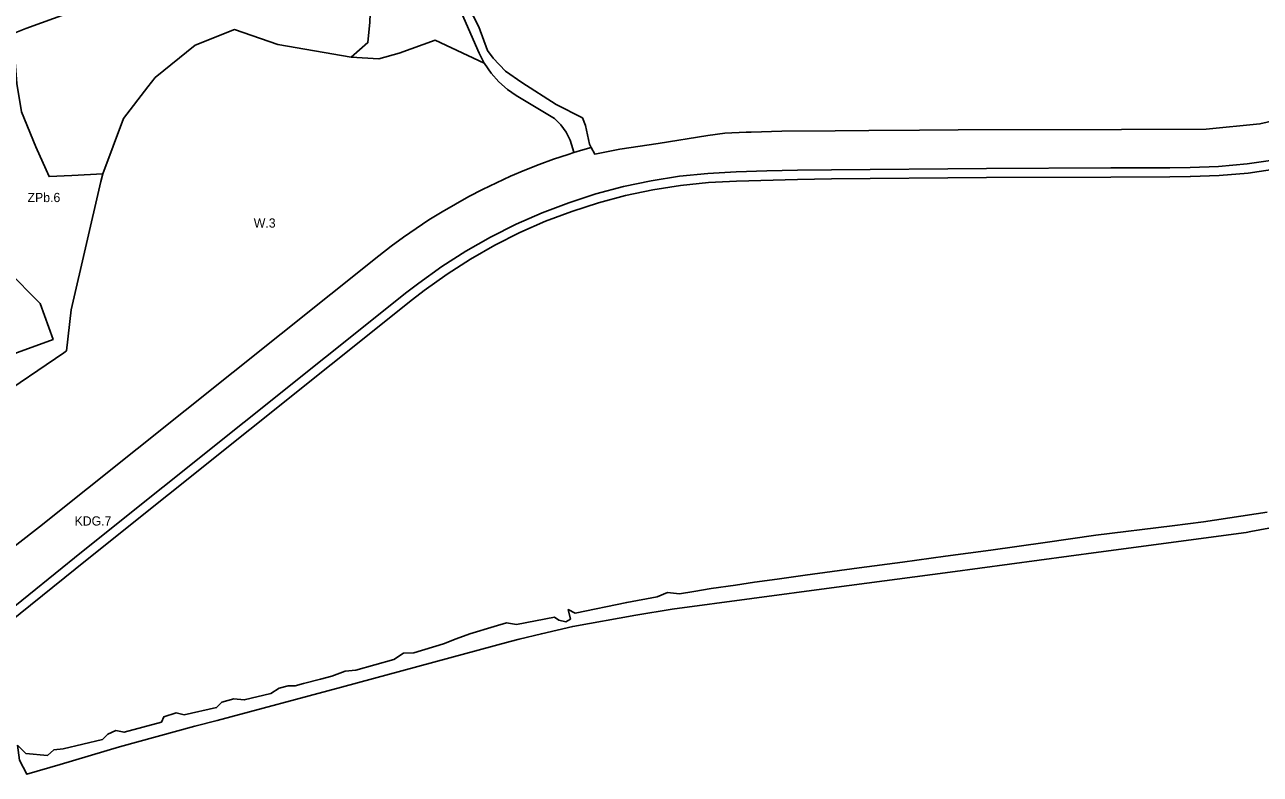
# Model space of a CAD drawing. Extents: x 7414808 to 7417449, y 5544732 to 5546764.
# Drawn here: x 7415896 to 7416568, y 5545062 to 5545469 of the extents above; entities that cross this region are included whole.
import ezdxf

# ---------------------------------------------------------------- set-up
doc = ezdxf.new("R2010")
doc.units = 0
for name, color, linetype in [('LIN_Linie Rozgraniczajace', 7, 'Continuous'), ('LIN_nieprzekraczale linie zabudowy', 7, 'Continuous'), ('TXT_Oznaczenia Przeznaczenia', 7, 'Continuous')]:
    doc.layers.add(name, color=color, linetype=linetype)

msp = doc.modelspace()

# ---------------------------------------------------------------- linework, layer by layer
at = {"layer": 'LIN_Linie Rozgraniczajace'}
for points in [[(7416073.13, 5545451.31), (7416082.32, 5545459.31), (7416083.36, 5545470.35), (7416084.04, 5545488.79), (7416084.22, 5545493.67), (7416088.82, 5545518.65), (7416087.12, 5545521.07), (7416090.29, 5545545.12), (7416089.03, 5545552.44), (7416091.1, 5545559), (7416097.95, 5545570.39), (7416098.86, 5545573.49), (7416101.69, 5545583.08), (7416103.92, 5545582.48), (7416110.68, 5545580.67), (7416114.9, 5545579.52)], [(7416114.9, 5545579.52), (7416114.69, 5545576.6), (7416114.12, 5545569.12), (7416113.66, 5545558.17), (7416113.18, 5545549.45), (7416112.43, 5545540.75), (7416112.1, 5545524.93), (7416112.39, 5545519.65), (7416113.47, 5545514.47), (7416115.32, 5545509.52), (7416117.83, 5545505.01), (7416121.06, 5545500.08), (7416126.17, 5545491.83), (7416142.87, 5545453.5), (7416145.64, 5545448.11)], [(7415938.67, 5545534.77), (7415935.27, 5545503.31), (7415933.52, 5545487.35), (7415932.44, 5545480.22), (7415919.83, 5545475.46), (7415896.22, 5545466.89), (7415888.9, 5545463.98), (7415889.93, 5545455.69), (7415891.31, 5545437.02), (7415893.94, 5545421.72), (7415901.72, 5545402.69), (7415907.31, 5545390.02), (7415908.9, 5545386.42), (7415921.31, 5545387.03), (7415938.04, 5545387.87)], [(7416203.8, 5545402.25), (7416202.88, 5545403.98), (7416200.74, 5545414.13), (7416199.13, 5545418.37), (7416184.71, 5545425.63), (7416166.06, 5545437.53), (7416157.09, 5545443.81), (7416150.47, 5545450.75), (7416147.44, 5545455.04), (7416142.62, 5545467.78), (7416134.07, 5545484.59), (7416128.45, 5545495.83), (7416117.88, 5545516.95), (7416120.04, 5545518.08)], [(7415938.04, 5545387.87), (7415949.41, 5545417.97), (7415962.67, 5545435.22), (7415966.57, 5545440.23), (7415988.27, 5545457.8), (7416009.74, 5545466.37), (7416033.34, 5545458.23), (7416073.13, 5545451.31)], [(7415879.66, 5545460.27), (7415876.71, 5545449.65), (7415865.22, 5545424.25), (7415868.44, 5545414.11), (7415875.83, 5545393.73), (7415874.66, 5545373.55), (7415872.37, 5545349.31), (7415902.54, 5545318.9), (7415903.97, 5545317.38), (7415911.08, 5545297.88), (7415872.14, 5545283.71)], [(7416073.13, 5545451.31), (7416088.19, 5545450.49), (7416099.38, 5545453.57), (7416118.93, 5545460.58), (7416145.64, 5545448.11)], [(7416145.64, 5545448.11), (7416145.75, 5545447.88), (7416149.33, 5545442.67), (7416153.53, 5545437.94), (7416158.29, 5545433.79), (7416162.99, 5545430.59), (7416183.89, 5545418.06), (7416187.35, 5545414.6), (7416190.21, 5545410.62), (7416192.37, 5545406.23), (7416193.8, 5545401.55), (7416194.26, 5545399.44)], [(7416203.8, 5545402.25), (7416205.71, 5545398.64), (7416219.36, 5545401.3), (7416240.16, 5545404.5), (7416267.25, 5545408.69), (7416276.53, 5545410.11), (7416288.16, 5545410.51), (7416290.75, 5545410.59), (7416307.47, 5545411.09), (7416336.58, 5545411.29), (7416354.77, 5545411.52), (7416382.4, 5545411.67), (7416403.41, 5545411.78), (7416492.23, 5545412.09), (7416538.31, 5545412.24), (7416567.53, 5545415.03), (7416585.83, 5545419.31)], [(7415883.84, 5545180.87), (7415891.33, 5545186.37), (7415903.74, 5545195.97), (7416088.24, 5545343.29), (7416095.01, 5545348.55), (7416101.71, 5545353.47), (7416108.53, 5545358.23), (7416115.54, 5545362.83), (7416122.67, 5545367.28), (7416129.91, 5545371.52), (7416137.25, 5545375.58), (7416144.7, 5545379.44), (7416152.24, 5545383.12), (7416159.88, 5545386.6), (7416167.6, 5545389.88), (7416175.41, 5545392.96), (7416183.29, 5545395.84), (7416191.24, 5545398.51), (7416194.26, 5545399.44)], [(7416194.26, 5545399.44), (7416199.26, 5545400.98), (7416203.8, 5545402.25)], [(7415883.49, 5545147.52), (7415926.53, 5545182.17), (7416103.57, 5545323.54), (7416109.96, 5545328.5), (7416122.55, 5545337.52), (7416135.6, 5545345.87), (7416149.06, 5545353.54), (7416162.9, 5545360.5), (7416177.08, 5545366.74), (7416191.56, 5545372.24), (7416206.3, 5545376.99), (7416221.28, 5545380.96), (7416236.43, 5545384.16), (7416251.74, 5545386.57), (7416267.14, 5545388.19), (7416282.61, 5545389.01), (7416299.27, 5545389.47), (7416315.92, 5545389.92), (7416334.42, 5545390.16), (7416418.84, 5545390.91), (7416486.37, 5545391.18), (7416518.47, 5545391.28), (7416529.63, 5545391.4), (7416545.11, 5545391.97), (7416560.54, 5545393.34), (7416575.88, 5545395.51)], [(7415878.87, 5545264.85), (7415916.98, 5545290.63), (7415918.31, 5545291.75), (7415920.92, 5545314.03), (7415937.07, 5545383.68), (7415938.04, 5545387.87)], [(7415891.69, 5545077.35), (7415896.32, 5545072.72), (7415908, 5545071.64), (7415911.47, 5545074.81), (7415916.49, 5545075.28), (7415937.85, 5545080.4), (7415940.76, 5545083.33), (7415945.15, 5545085.32), (7415949.71, 5545084.31), (7415959.84, 5545087.05), (7415969.95, 5545089.78), (7415971.31, 5545092.8), (7415977.94, 5545094.92), (7415982.36, 5545093.89), (7415999.97, 5545097.77), (7416002.88, 5545100.65), (7416009.32, 5545102.5), (7416015.06, 5545101.94), (7416029.47, 5545105.47), (7416034.03, 5545108.28), (7416038.9, 5545109.56), (7416042.55, 5545109.58), (7416042.7, 5545109.62), (7416047.33, 5545110.82), (7416056.57, 5545113.22), (7416062.78, 5545114.83), (7416069.94, 5545117.64), (7416075.69, 5545118.1), (7416096.38, 5545123.96), (7416101.76, 5545127.29), (7416107.07, 5545127.44), (7416107.31, 5545127.51), (7416123.35, 5545132.5), (7416130.35, 5545135.08), (7416137.7, 5545137.79), (7416150.93, 5545141.76), (7416157.75, 5545143.81), (7416163.16, 5545142.96), (7416183.86, 5545146.98), (7416186.2, 5545145.21), (7416190.01, 5545144.43), (7416192.51, 5545145.85), (7416191.29, 5545150.99), (7416194.99, 5545149.14), (7416223.11, 5545154.91), (7416239.58, 5545157.91), (7416245.28, 5545160.29), (7416251.74, 5545159.57), (7416259.65, 5545160.91), (7416269.1, 5545162.43), (7416282.33, 5545164.39), (7416292.69, 5545165.9), (7416305.01, 5545167.57), (7416320.2, 5545169.66), (7416349.6, 5545173.8), (7416373.13, 5545176.85), (7416396.56, 5545180.01), (7416421.23, 5545183.34), (7416450.82, 5545187.49), (7416478.25, 5545191.45), (7416519.78, 5545196.6), (7416536.88, 5545198.68), (7416571.44, 5545204.08)], [(7415891.69, 5545077.35), (7415892.76, 5545069.1), (7415896.72, 5545061.5), (7415914.97, 5545066.87), (7415947.19, 5545076.34), (7415988.24, 5545087.59), (7416000.33, 5545090.81), (7416067.93, 5545108.9), (7416159.73, 5545133.73), (7416164.61, 5545134.98), (7416176.73, 5545137.86), (7416193.72, 5545141.89), (7416228.15, 5545148.01), (7416247.85, 5545151.24), (7416334.49, 5545162.77), (7416398.97, 5545171.36), (7416479.74, 5545182.19), (7416560.12, 5545193.01), (7416562.54, 5545193.44), (7416572.38, 5545195.24)]]:
    msp.add_lwpolyline(points, dxfattribs=at)
at = {"layer": 'LIN_nieprzekraczale linie zabudowy'}
msp.add_lwpolyline([(7416576.7, 5545390.57), (7416561.11, 5545388.37), (7416545.42, 5545386.98), (7416529.81, 5545386.41), (7416529.68, 5545386.4), (7416518.51, 5545386.28), (7416486.39, 5545386.18), (7416418.87, 5545385.91), (7416334.48, 5545385.16), (7416316.02, 5545384.92), (7416282.81, 5545384.02), (7416267.53, 5545383.21), (7416252.39, 5545381.61), (7416237.34, 5545379.24), (7416222.43, 5545376.1), (7416207.71, 5545372.19), (7416193.21, 5545367.52), (7416178.97, 5545362.11), (7416165.03, 5545355.98), (7416151.42, 5545349.13), (7416138.19, 5545341.59), (7416125.36, 5545333.38), (7416112.95, 5545324.5), (7416106.64, 5545319.6), (7415929.65, 5545178.27), (7415886.63, 5545143.63)], dxfattribs=at)

# ---------------------------------------------------------------- texts
at = {"layer": 'TXT_Oznaczenia Przeznaczenia'}
for s, p in [('ZPb.6', (7415897.14, 5545372.57)), ('W.3', (7416020.22, 5545358.68)), ('KDG.7', (7415922.71, 5545196.72))]:
    msp.add_text(s, height=5, dxfattribs=at).set_placement(p)

doc.saveas('drawing.dxf')
